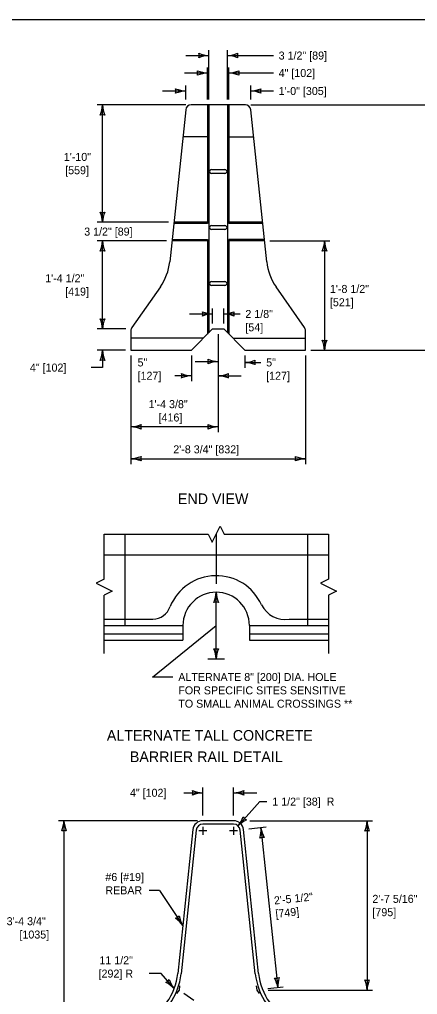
# Model space of a CAD drawing. Extents: x 49991.4 to 50021, y 49987.6 to 50011.4.
# Drawn here: x 50008.86 to 50011.85, y 49991.69 to 49999 of the extents above; entities that cross this region are included whole.
import ezdxf

# ---------------------------------------------------------------- set-up
doc = ezdxf.new("R2010")
doc.units = 0
for name, color, linetype in [('Level 1', 7, 'Continuous'), ('Level 2', 7, 'Continuous'), ('Level 3', 7, 'Continuous'), ('Level 4', 7, 'Continuous'), ('Level 6', 7, 'Continuous')]:
    doc.layers.add(name, color=color, linetype=linetype)

msp = doc.modelspace()

# ---------------------------------------------------------------- linework, layer by layer
at = {"layer": 'Level 1'}
for p, q in [((50010.1072, 49998.3228), (50009.9868, 49997.1814)), ((50010.555, 49998.3586), (50010.147, 49998.3586)), ((50010.2709, 49998.3586), (50010.2709, 49997.4688)), ((50010.281, 49998.3586), (50010.281, 49996.6507)), ((50010.421, 49998.3586), (50010.421, 49996.6507)), ((50010.4309, 49998.3586), (50010.4309, 49997.4688)), ((50010.7151, 49997.1814), (50010.5948, 49998.3228)), ((50010.2709, 49998.1186), (50010.0857, 49998.1186)), ((50010.4309, 49998.1186), (50010.6163, 49998.1186)), ((50010.3009, 49997.8736), (50010.4011, 49997.8736)), ((50010.4011, 49997.8441), (50010.3009, 49997.8441)), ((50010.2709, 49997.4688), (50010.0171, 49997.4688)), ((50010.2709, 49997.4788), (50010.0182, 49997.4788)), ((50010.3009, 49997.4536), (50010.4011, 49997.4536)), ((50010.6838, 49997.4788), (50010.4309, 49997.4788)), ((50010.6848, 49997.4688), (50010.4309, 49997.4688)), ((50010.4011, 49997.4241), (50010.3009, 49997.4241)), ((50010.271, 49997.3388), (50010.0034, 49997.3388)), ((50010.0045, 49997.3488), (50010.271, 49997.3488)), ((50010.271, 49997.3488), (50010.271, 49996.6405)), ((50010.4311, 49997.3488), (50010.4311, 49996.6404)), ((50010.6975, 49997.3488), (50010.4311, 49997.3488)), ((50010.6985, 49997.3387), (50010.4311, 49997.3387)), ((50009.9167, 49996.994), (50009.7032, 49996.689)), ((50010.3009, 49997.0336), (50010.4011, 49997.0336)), ((50010.4011, 49997.0041), (50010.3009, 49997.0041)), ((50010.9987, 49996.689), (50010.7852, 49996.994)), ((50009.696, 49996.666), (50009.696, 49996.5186)), ((50010.3085, 49996.6786), (50010.151, 49996.5186)), ((50010.3085, 49996.6786), (50010.3935, 49996.6786)), ((50010.3935, 49996.6786), (50010.551, 49996.5186)), ((50011.006, 49996.5186), (50011.006, 49996.666)), ((50009.696, 49996.5186), (50010.151, 49996.5186)), ((50010.551, 49996.5186), (50011.006, 49996.5186)), ((50009.6499, 49995.1408), (50009.6499, 49994.4543)), ((50010.336, 49995.1408), (50010.336, 49994.7661)), ((50011.0221, 49995.1408), (50011.0221, 49994.4543)), ((50009.494, 49994.9849), (50011.178, 49994.9849)), ((50009.494, 49994.5015), (50009.8605, 49994.5015)), ((50010.8827, 49994.5015), (50011.178, 49994.5015)), ((50010.0865, 49994.4543), (50010.0865, 49994.3452)), ((50010.5855, 49994.4543), (50010.5855, 49994.3452)), ((50009.494, 49994.3919), (50010.0865, 49994.3919)), ((50010.5855, 49994.3919), (50011.178, 49994.3919)), ((50009.494, 49994.3452), (50010.0865, 49994.3452)), ((50010.5855, 49994.3452), (50011.178, 49994.3452)), ((50010.4668, 49992.9901), (50010.2351, 49992.9901)), ((50010.1613, 49992.9238), (50010.0472, 49991.8452)), ((50010.1864, 49992.9212), (50010.0724, 49991.8425)), ((50010.4668, 49992.9649), (50010.2351, 49992.9649)), ((50010.6296, 49991.8425), (50010.5155, 49992.9212)), ((50010.6547, 49991.8452), (50010.5406, 49992.9238))]:
    msp.add_line(p, q, dxfattribs=at)
msp.add_lwpolyline([(49999.3835, 49998.9992), (50016.7501, 49998.9992), (50016.7501, 49987.7988), (49999.3835, 49987.7988)], close=True, dxfattribs=at)
for centre, radius, start, end in [((50010.336, 49994.4543), 0.3742, 24.5944, 157.68907), ((50010.336, 49994.4543), 0.2495, 0, 180), ((50009.8559, 49994.6434), 0.142, 271.85546, 340.63585), ((50010.8541, 49994.6977), 0.1983, 206.25708, 278.28472)]:
    msp.add_arc(centre, radius, start, end, dxfattribs=at)
for centre, major_axis, ratio, start_param, end_param in [((50010.147, 49998.3186), (-0.04, 0), 0.999982, 4.712389, 6.178105), ((50010.555, 49998.3186), (-0.04, 0), 0.999982, 3.246673, 4.712389), ((50010.3009, 49997.8589), (0.015, 0), 0.980989, 1.570796, 4.712389), ((50010.4011, 49997.8589), (0.015, 0), 0.980989, 4.712389, 7.853982), ((50010.3009, 49997.4389), (0.015, 0), 0.980989, 1.570796, 4.712389), ((50010.4011, 49997.4389), (0.015, 0), 0.980989, 4.712389, 7.853982), ((50009.589, 49997.2234), (0.4, 0), 0.999982, 5.672459, 6.178105), ((50011.1129, 49997.2234), (-0.4, 0), 0.999982, 0.10508, 0.610726), ((50010.3009, 49997.0189), (0.015, 0), 0.980989, 1.570796, 4.712389), ((50010.4011, 49997.0189), (0.015, 0), 0.980989, 4.712389, 7.853982), ((50009.736, 49996.666), (-0.04, 0), 0.999982, 5.672459, 6.283185), ((50010.966, 49996.666), (0.04, 0), 0.999982, 0, 0.610726), ((50010.2351, 49992.9161), (-0.0742, 0), 0.997211, 4.712389, 6.178105), ((50010.4668, 49992.9161), (0.0742, 0), 0.997211, 0.10508, 1.570796), ((50010.2351, 49992.9161), (-0.049, 0), 0.997211, 4.712389, 6.178105), ((50010.4668, 49992.9161), (-0.049, 0), 0.997211, 3.246673, 4.712389), ((50009.5873, 49991.8935), (0.4625, 0), 0.997211, 5.672459, 6.178105), ((50009.5873, 49991.8935), (0.4877, 0), 0.997211, 5.672459, 6.178105), ((50011.1146, 49991.8935), (-0.4877, 0), 0.997211, 0.10508, 0.610726), ((50011.1146, 49991.8935), (-0.4625, 0), 0.997211, 0.10508, 0.610726)]:
    msp.add_ellipse(centre, major_axis=major_axis, ratio=ratio, start_param=start_param, end_param=end_param, dxfattribs=at)
at = {"layer": 'Level 3'}
for p, q in [((50010.281, 49998.3986), (50010.281, 49998.7687)), ((50010.421, 49998.3986), (50010.421, 49998.7687)), ((50010.1075, 49998.7287), (50010.281, 49998.7287)), ((50010.421, 49998.7287), (50010.7648, 49998.7288)), ((50010.0975, 49998.5981), (50010.2709, 49998.5981)), ((50010.2709, 49998.3986), (50010.2709, 49998.6381)), ((50010.4309, 49998.3986), (50010.431, 49998.6381)), ((50010.431, 49998.5981), (50010.7648, 49998.5981)), ((50009.9338, 49998.4632), (50010.1072, 49998.4632)), ((50010.1072, 49998.3986), (50010.1072, 49998.5032)), ((50010.5948, 49998.3986), (50010.5948, 49998.5031)), ((50010.5948, 49998.4631), (50010.7648, 49998.4631)), ((50010.107, 49998.3586), (50009.4429, 49998.3586)), ((50009.4829, 49997.4788), (50009.4829, 49998.3586)), ((50010.595, 49998.3586), (50011.9984, 49998.3586)), ((50009.9782, 49997.4788), (50009.4429, 49997.4788)), ((50009.9634, 49997.3388), (50009.4429, 49997.3388)), ((50009.4829, 49996.6786), (50009.4829, 49997.3388)), ((50010.7385, 49997.3387), (50011.1894, 49997.3387)), ((50011.1494, 49997.3387), (50011.1494, 49996.5186)), ((50010.135, 49996.791), (50010.3085, 49996.791)), ((50010.3085, 49996.7186), (50010.3085, 49996.831)), ((50010.3935, 49996.7186), (50010.3935, 49996.831)), ((50010.3935, 49996.791), (50010.5149, 49996.791)), ((50009.6578, 49996.6786), (50009.4429, 49996.6786)), ((50010.351, 49996.6386), (50010.351, 49995.9047)), ((50009.656, 49996.5186), (50009.4429, 49996.5186)), ((50009.4829, 49996.5186), (50009.4829, 49996.3889)), ((50009.696, 49996.4786), (50009.696, 49995.6658)), ((50010.151, 49996.4786), (50010.151, 49996.2876)), ((50010.551, 49996.4786), (50010.551, 49996.3876)), ((50011.006, 49996.4786), (50011.006, 49995.6658)), ((50011.046, 49996.5186), (50011.9984, 49996.5186)), ((50010.1775, 49996.4349), (50010.351, 49996.4349)), ((50010.551, 49996.4276), (50010.671, 49996.4276)), ((50009.4829, 49996.3889), (50009.3972, 49996.3889)), ((50010.151, 49996.3276), (50010.0261, 49996.3276)), ((50010.351, 49996.3276), (50010.5244, 49996.3276)), ((50010.351, 49995.9447), (50009.696, 49995.9447)), ((50009.696, 49995.7058), (50011.006, 49995.7058)), ((50010.336, 49994.2048), (50010.336, 49994.7037)), ((50009.857, 49994.0685), (50010.336, 49994.4543)), ((50010.2736, 49994.2048), (50010.3984, 49994.2048)), ((50010.0115, 49994.0685), (50009.857, 49994.0685)), ((50010.0935, 49993.2004), (50010.2351, 49993.2004)), ((50010.2351, 49993.0301), (50010.2351, 49993.2404)), ((50010.4668, 49993.0301), (50010.4668, 49993.2404)), ((50010.4668, 49993.2004), (50010.6403, 49993.2004)), ((50010.5001, 49992.9519), (50010.6643, 49993.1339)), ((50010.6643, 49993.1339), (50010.7172, 49993.1339)), ((50010.1951, 49992.9901), (50009.1536, 49992.9901)), ((50009.1936, 49992.9901), (50009.1936, 49991.385)), ((50010.5888, 49992.9892), (50011.5083, 49992.9892)), ((50011.4683, 49992.9892), (50011.4683, 49991.7209)), ((50010.2651, 49992.9161), (50010.2051, 49992.9161)), ((50010.2351, 49992.9461), (50010.2351, 49992.8861)), ((50010.4968, 49992.9161), (50010.4368, 49992.9161)), ((50010.4668, 49992.9461), (50010.4668, 49992.8861)), ((50010.7119, 49992.9418), (50010.5804, 49992.928)), ((50010.6721, 49992.9377), (50010.799, 49991.7373)), ((50009.9111, 49992.4688), (50009.8335, 49992.4688)), ((50009.9111, 49992.4688), (50010.0854, 49992.2061)), ((50009.9239, 49991.8446), (50009.8335, 49991.8444)), ((50010.0205, 49991.732), (50009.9239, 49991.8446)), ((50010.0599, 49991.7209), (50010.0633, 49991.7527)), ((50010.6426, 49991.7209), (50010.6392, 49991.7527)), ((50010.8388, 49991.7415), (50010.7239, 49991.7294)), ((50010.0414, 49991.6945), (50010.0599, 49991.7209)), ((50010.0927, 49991.698), (50010.1678, 49991.6455)), ((50010.6611, 49991.6945), (50010.6426, 49991.7209)), ((50010.7258, 49991.7208), (50011.5083, 49991.7209))]:
    msp.add_line(p, q, dxfattribs=at)
for centre, radius, start, end in [((50010.2901, 49998.9508), 0.2223, 247.45601, 267.63952), ((50010.1528, 49998.7287), 0.0548, 342.13882, 17.86118), ((50010.4095, 49998.9614), 0.233, 272.82731, 292.07716), ((50010.5492, 49998.7287), 0.0548, 162.13882, 197.86118), ((50010.2925, 49998.496), 0.233, 92.82731, 112.07716), ((50010.4118, 49998.5066), 0.2223, 67.45601, 87.63952), ((50010.2801, 49998.8202), 0.2223, 247.45601, 267.63952), ((50010.1427, 49998.5981), 0.0548, 342.13882, 17.86118), ((50010.2824, 49998.3653), 0.233, 92.82731, 112.07716), ((50010.4195, 49998.8308), 0.233, 272.82731, 292.07716), ((50010.4218, 49998.3759), 0.2223, 67.45601, 87.63952), ((50010.5592, 49998.5981), 0.0548, 162.13882, 197.86118), ((50010.1163, 49998.6853), 0.2223, 247.45601, 267.63952), ((50009.979, 49998.4632), 0.0548, 342.13882, 17.86118), ((50010.1187, 49998.2305), 0.233, 92.82731, 112.07716), ((50010.5833, 49998.6959), 0.233, 272.82731, 292.07716), ((50010.5856, 49998.241), 0.2223, 67.45601, 87.63952), ((50010.723, 49998.4631), 0.0548, 162.13882, 197.86118), ((50009.2608, 49998.3678), 0.2223, 337.45601, 357.63952), ((50009.7157, 49998.3701), 0.233, 182.82731, 202.07716), ((50009.4829, 49998.2304), 0.0548, 72.13882, 107.86118), ((50009.4829, 49997.607), 0.0548, 252.13882, 287.86118), ((50009.2502, 49997.4673), 0.233, 2.82731, 22.07716), ((50009.7051, 49997.4697), 0.2223, 157.45601, 177.63952), ((50009.2608, 49997.348), 0.2223, 337.45601, 357.63952), ((50009.7157, 49997.3503), 0.233, 182.82731, 202.07716), ((50010.9272, 49997.3479), 0.2223, 337.45601, 357.63952), ((50011.3821, 49997.3502), 0.233, 182.82731, 202.07716), ((50009.4829, 49997.2106), 0.0548, 72.13882, 107.86118), ((50011.1494, 49997.2105), 0.0548, 72.13882, 107.86118), ((50010.3176, 49997.0131), 0.2223, 247.45601, 267.63952), ((50010.1803, 49996.791), 0.0548, 342.13882, 17.86118), ((50010.32, 49996.5583), 0.233, 92.82731, 112.07716), ((50010.382, 49997.0237), 0.233, 272.82731, 292.07716), ((50010.3843, 49996.5689), 0.2223, 67.45601, 87.63952), ((50010.5217, 49996.791), 0.0548, 162.13882, 197.86118), ((50009.4829, 49996.8068), 0.0548, 252.13882, 287.86118), ((50009.2502, 49996.6671), 0.233, 2.82731, 22.07716), ((50009.7051, 49996.6695), 0.2223, 157.45601, 177.63952), ((50011.1494, 49996.6469), 0.0548, 252.13882, 287.86118), ((50010.9166, 49996.5071), 0.233, 2.82731, 22.07716), ((50011.3715, 49996.5095), 0.2223, 157.45601, 177.63952), ((50009.2608, 49996.5278), 0.2223, 337.45601, 357.63952), ((50009.7157, 49996.5301), 0.233, 182.82731, 202.07716), ((50009.4829, 49996.3904), 0.0548, 72.13882, 107.86118), ((50010.3601, 49996.6571), 0.2223, 247.45601, 267.63952), ((50010.2228, 49996.4349), 0.0548, 342.13882, 17.86118), ((50010.3625, 49996.2022), 0.233, 92.82731, 112.07716), ((50010.5395, 49996.6603), 0.233, 272.82731, 292.07716), ((50010.5418, 49996.2055), 0.2223, 67.45601, 87.63952), ((50010.6792, 49996.4276), 0.0548, 162.13882, 197.86118), ((50010.1601, 49996.5498), 0.2223, 247.45601, 267.63952), ((50010.0228, 49996.3276), 0.0548, 342.13882, 17.86118), ((50010.3395, 49996.5603), 0.233, 272.82731, 292.07716), ((50010.4792, 49996.3276), 0.0548, 162.13882, 197.86118), ((50010.1625, 49996.0949), 0.233, 92.82731, 112.07716), ((50010.3418, 49996.1055), 0.2223, 67.45601, 87.63952), ((50009.6845, 49996.1774), 0.233, 272.82731, 292.07716), ((50009.6868, 49995.7225), 0.2223, 67.45601, 87.63952), ((50009.8242, 49995.9447), 0.0548, 162.13882, 197.86118), ((50010.3601, 49996.1668), 0.2223, 247.45601, 267.63952), ((50010.2228, 49995.9447), 0.0548, 342.13882, 17.86118), ((50010.3625, 49995.712), 0.233, 92.82731, 112.07716), ((50009.6845, 49995.9386), 0.233, 272.82731, 292.07716), ((50009.6868, 49995.4837), 0.2223, 67.45601, 87.63952), ((50009.8242, 49995.7058), 0.0548, 162.13882, 197.86118), ((50011.0151, 49995.928), 0.2223, 247.45601, 267.63952), ((50010.8778, 49995.7058), 0.0548, 342.13882, 17.86118), ((50011.0175, 49995.4731), 0.233, 92.82731, 112.07716), ((50010.1139, 49994.7129), 0.2223, 337.45601, 357.63952), ((50010.5687, 49994.7152), 0.233, 182.82731, 202.07716), ((50010.336, 49994.5755), 0.0548, 72.13882, 107.86118), ((50010.336, 49994.333), 0.0548, 252.13882, 287.86118), ((50010.1033, 49994.1933), 0.233, 2.82731, 22.07716), ((50010.5581, 49994.1957), 0.2223, 157.45601, 177.63952), ((50010.2443, 49993.4225), 0.2223, 247.45601, 267.63952), ((50010.1069, 49993.2004), 0.0548, 342.13882, 17.86118), ((50010.2466, 49992.9677), 0.233, 92.82731, 112.07716), ((50010.4553, 49993.4331), 0.233, 272.82731, 292.07716), ((50010.4577, 49992.9782), 0.2223, 67.45601, 87.63952), ((50010.595, 49993.2004), 0.0548, 162.13882, 197.86118), ((50008.9715, 49992.9992), 0.2223, 337.45601, 357.63952), ((50009.4263, 49993.0016), 0.233, 182.82731, 202.07716), ((50010.3196, 49993.0993), 0.233, 320.75806, 340.00791), ((50010.6588, 49992.7963), 0.2223, 115.38676, 135.57026), ((50010.586, 49993.0471), 0.0548, 210.06956, 245.79192), ((50011.2461, 49992.9984), 0.2223, 337.45601, 357.63952), ((50011.701, 49993.0007), 0.233, 182.82731, 202.07716), ((50009.1936, 49992.8619), 0.0548, 72.13882, 107.86118), ((50010.4502, 49992.9234), 0.2223, 343.49339, 3.6769), ((50010.9023, 49992.9736), 0.233, 188.86469, 208.11454), ((50011.4683, 49992.861), 0.0548, 72.13882, 107.86118), ((50010.6856, 49992.8102), 0.0548, 78.1762, 113.89856), ((50010.0145, 49992.3129), 0.0548, 285.70074, 321.4231), ((50009.8978, 49992.0678), 0.233, 36.38923, 55.63908), ((50010.2756, 49992.3212), 0.2223, 191.01793, 211.20144), ((50009.937, 49991.8293), 0.0548, 292.74308, 328.46544), ((50010.1951, 49991.8696), 0.2223, 198.06027, 218.24378), ((50010.7855, 49991.8648), 0.0548, 258.1762, 293.89856), ((50010.5688, 49991.7014), 0.233, 8.86469, 28.11454), ((50011.0209, 49991.7516), 0.2223, 163.49339, 183.6769), ((50011.4683, 49991.8491), 0.0548, 252.13882, 287.86118), ((50011.2356, 49991.7094), 0.233, 2.82731, 22.07716), ((50011.6904, 49991.7117), 0.2223, 157.45601, 177.63952), ((50009.8513, 49991.5718), 0.233, 43.43157, 62.68142)]:
    msp.add_arc(centre, radius, start, end, dxfattribs=at)
at = {"layer": 'Level 4'}
for p, q in [((50010.2396, 49996.6086), (50009.696, 49996.6086)), ((50010.4624, 49996.6086), (50011.006, 49996.6086)), ((50009.494, 49994.4543), (50010.0865, 49994.4543)), ((50010.5855, 49994.4543), (50011.178, 49994.4543))]:
    msp.add_line(p, q, dxfattribs=at)
for points in [[(50010.276, 49995.1408), (50010.306, 49995.0808), (50010.366, 49995.2008), (50010.396, 49995.1408)], [(50009.494, 49994.803), (50009.434, 49994.773), (50009.554, 49994.713), (50009.494, 49994.683)], [(50011.178, 49994.803), (50011.118, 49994.773), (50011.238, 49994.713), (50011.178, 49994.683)]]:
    msp.add_lwpolyline(points, dxfattribs=at)
at = {"layer": 'Level 6'}
for p, q in [((50009.494, 49994.803), (50009.494, 49995.1408)), ((50009.494, 49995.1408), (50010.276, 49995.1408)), ((50010.396, 49995.1408), (50011.178, 49995.1408)), ((50011.178, 49995.1408), (50011.178, 49994.803)), ((50009.494, 49994.2452), (50009.494, 49994.683)), ((50011.178, 49994.683), (50011.178, 49994.2452))]:
    msp.add_line(p, q, dxfattribs=at)

# ---------------------------------------------------------------- texts
at = {"layer": 'Level 2'}
for s, height, p in [('3 1/2" [89]', 0.06, (50010.8048, 49998.6988)), ('4" [102]', 0.06, (50010.8048, 49998.5681)), ('1\'-0" [305]', 0.06, (50010.8048, 49998.4331)), ('1\'-10"', 0.06, (50009.1921, 49997.9388)), ('[559]', 0.06, (50009.2025, 49997.8388)), ('3 1/2" [89]', 0.06, (50009.3453, 49997.3788)), ('1\'-4 1/2"', 0.06, (50009.0526, 49997.0288)), ('[419]', 0.06, (50009.2025, 49996.9288)), ('1\'-8 1/2"', 0.06, (50011.1894, 49996.9488)), ('[521]', 0.06, (50011.1894, 49996.8488)), ('2 1/8"', 0.06, (50010.5549, 49996.761)), ('[54]', 0.06, (50010.5549, 49996.661)), ('4" [102]', 0.06, (50008.9377, 49996.3589)), ('5"', 0.06, (50009.7457, 49996.3976)), ('5"', 0.06, (50010.711, 49996.3976)), ('[127]', 0.06, (50009.7457, 49996.2976)), ('[127]', 0.06, (50010.711, 49996.2976)), ('1\'-4 3/8"', 0.06, (50009.8284, 49996.0847)), ('[416]', 0.06, (50009.9034, 49995.9847)), ('2\'-8 3/4" [832]', 0.06, (50010.0138, 49995.7458)), ('END VIEW', 0.08, (50010.0486, 49995.3647)), ('ALTERNATE 8" [200] DIA. HOLE', 0.06, (50010.0515, 49994.0385)), ('FOR SPECIFIC SITES SENSITIVE', 0.06, (50010.0515, 49993.9385)), ('TO SMALL ANIMAL CROSSINGS **', 0.06, (50010.0515, 49993.8385)), ('ALTERNATE TALL CONCRETE', 0.08, (50009.5152, 49993.5907)), ('BARRIER RAIL DETAIL', 0.08, (50009.6878, 49993.4307)), ('4" [102]', 0.06, (50009.6885, 49993.1704)), ('1 1/2" [38]  R', 0.06, (50010.7572, 49993.1041)), ('#6 [#19]', 0.06, (50009.504, 49992.5388)), ('REBAR', 0.06, (50009.504, 49992.4388)), ('2\'-7 5/16"', 0.06, (50011.5083, 49992.375)), ('[795]', 0.06, (50011.5083, 49992.275)), ('3\'-4 3/4"', 0.06, (50008.7632, 49992.2073)), ('[1035]', 0.06, (50008.8593, 49992.1073)), ('11 1/2"', 0.06, (50009.4593, 49991.9144)), ('[292] R', 0.06, (50009.4531, 49991.8144))]:
    msp.add_text(s, height=height, dxfattribs=at).set_placement(p)
for s, p in [('2\'-5 1/2"', (50010.7732, 49992.3621)), ('[749]', (50010.7836, 49992.2626))]:
    msp.add_text(s, height=0.06, rotation=5.92777, dxfattribs=at).set_placement(p)

doc.saveas('drawing.dxf')
